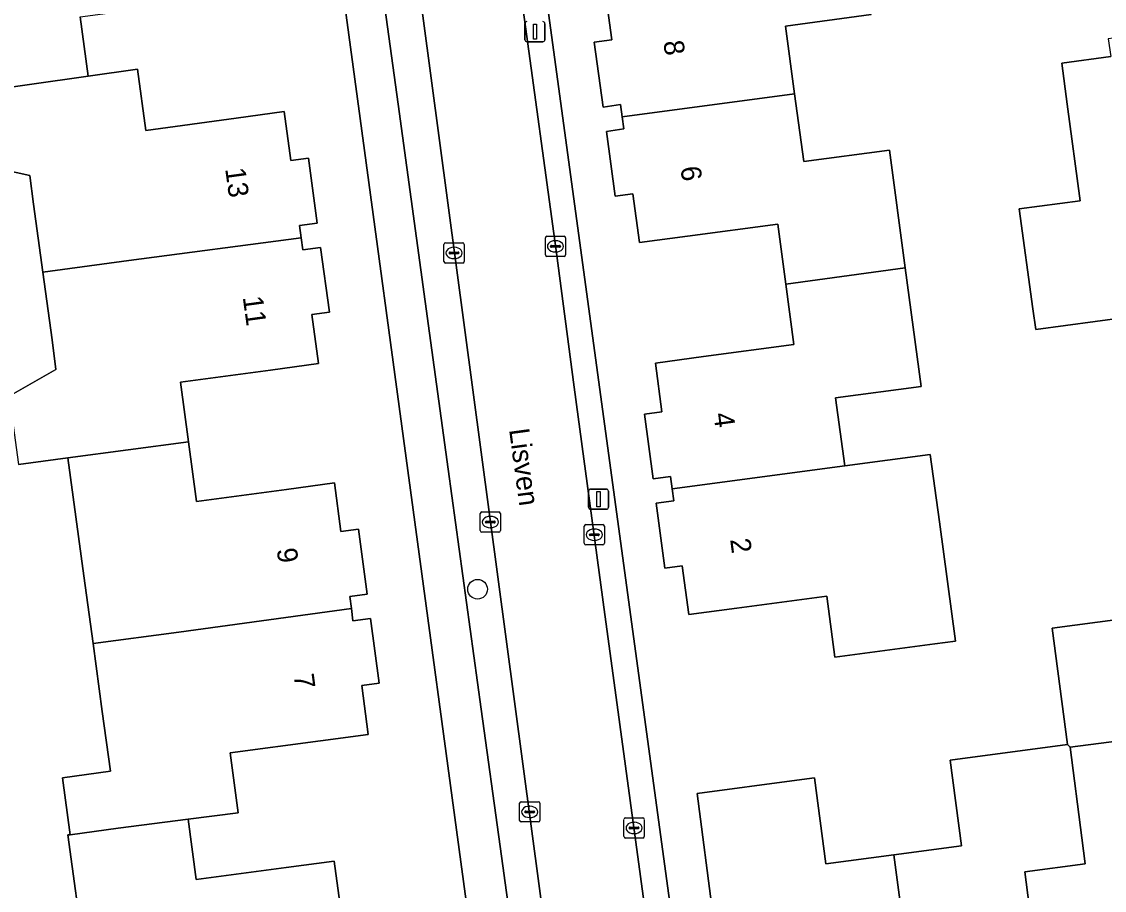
# Model space of a CAD drawing. Extents: x 163426 to 164192, y 380329 to 381641.
# Drawn here: x 163600.9 to 163654.6, y 381389.6 to 381432.7 of the extents above; entities that cross this region are included whole.
import ezdxf

# ---------------------------------------------------------------- set-up
doc = ezdxf.new("R2010")
doc.units = 0
for name, color, linetype in [('IMGEO_Boom', 7, 'Continuous'), ('IMGEO_Erf', 7, 'Continuous'), ('IMGEO_Kolk', 7, 'Continuous'), ('IMGEO_Lichtmast', 7, 'Continuous'), ('IMGEO_Openbare_ruimte_label', 7, 'Continuous'), ('IMGEO_Pand', 7, 'Continuous'), ('IMGEO_Pand_nummerreeks', 7, 'Continuous'), ('IMGEO_Parkeervlak_open', 7, 'Continuous'), ('IMGEO_Rijbaan_lokaal_open', 7, 'Continuous'), ('IMGEO_Voetpad_open', 7, 'Continuous')]:
    doc.layers.add(name, color=color, linetype=linetype)

msp = doc.modelspace()

# ---------------------------------------------------------------- linework, layer by layer
at = {"layer": 'IMGEO_Boom'}
msp.add_circle((163623.502, 381404.563), 0.489, dxfattribs=at)
at = {"layer": 'IMGEO_Erf'}
for points in [[(163625.429, 381370.672), (163614.908, 381448.295)], [(163625.846, 381441.76), (163634.711, 381376.758)], [(163643.031, 381433.061), (163638.779, 381432.489), (163639.232, 381429.12), (163639.683, 381425.765), (163643.935, 381426.337), (163644.72, 381420.495), (163645.51, 381414.622), (163641.264, 381414.051), (163641.717, 381410.682), (163645.964, 381411.246), (163646.413, 381407.908), (163647.209, 381401.991), (163646.189, 381401.855), (163641.232, 381401.193), (163640.825, 381404.228), (163636.359, 381403.629), (163633.98, 381403.31), (163633.66, 381405.731), (163632.79, 381405.616), (163632.365, 381408.827), (163633.235, 381408.942), (163633.155, 381409.544), (163633.075, 381410.148), (163632.206, 381410.033), (163631.781, 381413.244), (163632.65, 381413.359), (163632.33, 381415.78), (163634.709, 381416.099), (163639.196, 381416.7), (163638.794, 381419.697), (163638.396, 381422.67), (163633.909, 381422.069), (163631.53, 381421.75), (163631.2, 381424.173), (163630.33, 381424.054), (163629.892, 381427.268), (163630.762, 381427.387), (163630.68, 381427.989), (163630.598, 381428.593), (163629.728, 381428.475), (163629.29, 381431.689), (163630.16, 381431.807), (163629.83, 381434.23)], [(163603.784, 381432.938), (163604.182, 381430.011), (163606.633, 381430.344), (163607.044, 381427.318), (163611.522, 381427.927), (163613.9, 381428.25), (163614.232, 381425.821), (163615.105, 381425.941), (163615.545, 381422.719), (163614.673, 381422.6), (163614.756, 381421.994), (163614.838, 381421.39), (163615.711, 381421.51), (163616.15, 381418.298), (163615.278, 381418.179), (163615.61, 381415.75), (163613.232, 381415.429), (163608.765, 381414.827), (163609.163, 381411.874), (163609.563, 381408.912), (163614.019, 381409.512), (163616.398, 381409.833), (163616.723, 381407.42), (163617.594, 381407.537), (163618.027, 381404.322), (163617.157, 381404.205), (163617.239, 381403.601), (163617.32, 381402.998), (163618.19, 381403.116), (163618.624, 381399.901), (163617.753, 381399.783), (163618.08, 381397.36), (163615.701, 381397.044), (163611.226, 381396.451), (163611.621, 381393.475), (163609.14, 381393.159), (163609.536, 381390.171), (163614.011, 381390.764), (163616.39, 381391.08), (163616.721, 381388.652)], [(163657.086, 381418.241), (163651.194, 381417.436), (163651.054, 381418.466), (163650.38, 381423.42), (163653.398, 381423.822), (163652.76, 381428.618), (163652.49, 381430.65), (163654.913, 381430.978)], [(163600.263, 381414.138), (163602.585, 381415.466), (163602.388, 381416.923), (163601.932, 381420.287), (163601.476, 381423.658), (163601.284, 381425.078), (163598.705, 381425.644)], [(163602.901, 381395.213), (163605.283, 381395.536), (163604.882, 381398.5), (163604.425, 381401.873), (163603.97, 381405.235), (163603.179, 381411.077), (163600.723, 381410.745)], [(163635.18, 381388.45), (163634.39, 381394.44), (163639.348, 381395.093), (163640.221, 381395.208), (163640.782, 381390.95), (163644.152, 381391.394), (163647.514, 381391.837), (163646.954, 381396.094), (163652.765, 381396.859), (163652.006, 381402.631), (163657.886, 381403.405)], [(163655.84, 381397.119), (163652.894, 381396.738), (163653.477, 381392.239), (163653.644, 381390.947), (163650.648, 381390.559), (163651.232, 381386.05)], [(163603.98, 381386.466), (163603.179, 381392.378), (163603.283, 381392.392), (163602.901, 381395.213)]]:
    msp.add_lwpolyline(points, dxfattribs=at)
at = {"layer": 'IMGEO_Kolk'}
for p, q in [((163626.865, 381421.14), (163626.865, 381421.992)), ((163626.94, 381422.066), (163627.792, 381422.066)), ((163627.353, 381421.846), (163627.378, 381421.846)), ((163627.866, 381421.992), (163627.866, 381421.14)), ((163621.835, 381420.813), (163621.835, 381421.665)), ((163621.91, 381421.739), (163622.762, 381421.739)), ((163622.137, 381421.282), (163622.535, 381421.282)), ((163622.323, 381421.519), (163622.348, 381421.519)), ((163622.836, 381421.665), (163622.836, 381420.813)), ((163627.124, 381421.56), (163627.124, 381421.572)), ((163627.562, 381421.523), (163627.164, 381421.523)), ((163627.167, 381421.609), (163627.565, 381421.609)), ((163627.376, 381421.286), (163627.351, 381421.286)), ((163627.608, 381421.572), (163627.608, 381421.56)), ((163622.762, 381420.739), (163621.91, 381420.739)), ((163622.094, 381421.233), (163622.094, 381421.245)), ((163622.532, 381421.196), (163622.134, 381421.196)), ((163622.346, 381420.959), (163622.321, 381420.959)), ((163622.578, 381421.245), (163622.578, 381421.233)), ((163627.792, 381421.066), (163626.94, 381421.066)), ((163623.71, 381408.394), (163624.562, 381408.394)), ((163623.635, 381407.468), (163623.635, 381408.32)), ((163623.894, 381407.888), (163623.894, 381407.9)), ((163624.332, 381407.851), (163623.934, 381407.851)), ((163623.937, 381407.937), (163624.335, 381407.937)), ((163624.123, 381408.174), (163624.148, 381408.174)), ((163624.378, 381407.9), (163624.378, 381407.888)), ((163624.636, 381408.32), (163624.636, 381407.468)), ((163624.562, 381407.394), (163623.71, 381407.394)), ((163624.146, 381407.614), (163624.121, 381407.614)), ((163628.794, 381406.84), (163628.794, 381407.692)), ((163628.869, 381407.766), (163629.721, 381407.766)), ((163629.096, 381407.309), (163629.494, 381407.309)), ((163629.282, 381407.546), (163629.307, 381407.546)), ((163629.795, 381407.692), (163629.795, 381406.84)), ((163629.721, 381406.766), (163628.869, 381406.766)), ((163629.053, 381407.26), (163629.053, 381407.272)), ((163629.491, 381407.223), (163629.093, 381407.223)), ((163629.305, 381406.986), (163629.28, 381406.986)), ((163629.537, 381407.272), (163629.537, 381407.26)), ((163625.588, 381393.097), (163625.588, 381393.949)), ((163625.663, 381394.023), (163626.515, 381394.023)), ((163626.589, 381393.949), (163626.589, 381393.097)), ((163625.847, 381393.517), (163625.847, 381393.529)), ((163626.285, 381393.48), (163625.887, 381393.48)), ((163625.89, 381393.566), (163626.288, 381393.566)), ((163626.076, 381393.803), (163626.101, 381393.803)), ((163626.331, 381393.529), (163626.331, 381393.517)), ((163626.515, 381393.023), (163625.663, 381393.023)), ((163626.099, 381393.243), (163626.074, 381393.243)), ((163630.766, 381392.302), (163630.766, 381393.154)), ((163630.841, 381393.228), (163631.693, 381393.228)), ((163631.254, 381393.008), (163631.279, 381393.008)), ((163631.767, 381393.154), (163631.767, 381392.302)), ((163631.025, 381392.722), (163631.025, 381392.734)), ((163631.463, 381392.685), (163631.065, 381392.685)), ((163631.068, 381392.771), (163631.466, 381392.771)), ((163631.277, 381392.448), (163631.252, 381392.448)), ((163631.509, 381392.734), (163631.509, 381392.722)), ((163631.693, 381392.228), (163630.841, 381392.228))]:
    msp.add_line(p, q, dxfattribs=at)
for points in [[(163626.865, 381421.14), (163626.865, 381421.992)], [(163626.94, 381422.066), (163627.792, 381422.066)], [(163627.866, 381421.992), (163627.866, 381421.14)], [(163621.835, 381420.813), (163621.835, 381421.665)], [(163621.91, 381421.739), (163622.762, 381421.739)], [(163622.836, 381421.665), (163622.836, 381420.813)], [(163622.762, 381420.739), (163621.91, 381420.739)], [(163627.792, 381421.066), (163626.94, 381421.066)], [(163623.71, 381408.394), (163624.562, 381408.394)], [(163623.635, 381407.468), (163623.635, 381408.32)], [(163624.636, 381408.32), (163624.636, 381407.468)], [(163624.562, 381407.394), (163623.71, 381407.394)], [(163628.794, 381406.84), (163628.794, 381407.692)], [(163628.869, 381407.766), (163629.721, 381407.766)], [(163629.795, 381407.692), (163629.795, 381406.84)], [(163629.721, 381406.766), (163628.869, 381406.766)], [(163625.588, 381393.097), (163625.588, 381393.949)], [(163625.663, 381394.023), (163626.515, 381394.023)], [(163626.589, 381393.949), (163626.589, 381393.097)], [(163626.515, 381393.023), (163625.663, 381393.023)], [(163630.766, 381392.302), (163630.766, 381393.154)], [(163630.841, 381393.228), (163631.693, 381393.228)], [(163631.767, 381393.154), (163631.767, 381392.302)], [(163631.693, 381392.228), (163630.841, 381392.228)]]:
    msp.add_lwpolyline(points, dxfattribs=at)
for centre, radius, start, end in [((163626.942, 381421.99), 0.0765, 91.552, 178.448), ((163626.942, 381421.99), 0.0765, 91.552, 178.448), ((163627.79, 381421.99), 0.0765, 1.552, 88.448), ((163627.79, 381421.99), 0.0765, 1.552, 88.448), ((163621.912, 381421.663), 0.0765, 91.552, 178.448), ((163621.912, 381421.663), 0.0765, 91.552, 178.448), ((163622.134, 381421.242), 0.0403, 85.8775, 175.7526), ((163622.539, 381421.244), 0.0386, 1.7309, 96.639), ((163622.76, 381421.663), 0.0765, 1.552, 88.448), ((163622.76, 381421.663), 0.0765, 1.552, 88.448), ((163627.164, 381421.569), 0.0403, 85.8775, 175.7526), ((163627.161, 381421.559), 0.0366, 178.938, 274.7102), ((163627.565, 381421.566), 0.043, 264.8664, 352.4533), ((163627.569, 381421.571), 0.0386, 1.7309, 96.639), ((163621.912, 381420.815), 0.0765, 181.552, 268.448), ((163621.912, 381420.815), 0.0765, 181.552, 268.448), ((163622.131, 381421.232), 0.0366, 178.938, 274.7102), ((163622.535, 381421.239), 0.043, 264.8664, 352.4533), ((163622.76, 381420.815), 0.0765, 271.552, 358.448), ((163622.76, 381420.815), 0.0765, 271.552, 358.448), ((163626.942, 381421.142), 0.0765, 181.552, 268.448), ((163626.942, 381421.142), 0.0765, 181.552, 268.448), ((163627.79, 381421.142), 0.0765, 271.552, 358.448), ((163627.79, 381421.142), 0.0765, 271.552, 358.448), ((163623.712, 381408.318), 0.0765, 91.552, 178.448), ((163623.712, 381408.318), 0.0765, 91.552, 178.448), ((163624.56, 381408.318), 0.0765, 1.552, 88.448), ((163624.56, 381408.318), 0.0765, 1.552, 88.448), ((163623.934, 381407.897), 0.0403, 85.8775, 175.7526), ((163623.931, 381407.887), 0.0366, 178.938, 274.7102), ((163624.335, 381407.894), 0.043, 264.8664, 352.4533), ((163624.339, 381407.899), 0.0386, 1.7309, 96.639), ((163623.712, 381407.47), 0.0765, 181.552, 268.448), ((163623.712, 381407.47), 0.0765, 181.552, 268.448), ((163624.56, 381407.47), 0.0765, 271.552, 358.448), ((163624.56, 381407.47), 0.0765, 271.552, 358.448), ((163628.871, 381407.69), 0.0765, 91.552, 178.448), ((163628.871, 381407.69), 0.0765, 91.552, 178.448), ((163629.093, 381407.269), 0.0403, 85.8775, 175.7526), ((163629.498, 381407.271), 0.0386, 1.7309, 96.639), ((163629.719, 381407.69), 0.0765, 1.552, 88.448), ((163629.719, 381407.69), 0.0765, 1.552, 88.448), ((163628.871, 381406.842), 0.0765, 181.552, 268.448), ((163628.871, 381406.842), 0.0765, 181.552, 268.448), ((163629.09, 381407.259), 0.0366, 178.938, 274.7102), ((163629.494, 381407.266), 0.043, 264.8664, 352.4533), ((163629.719, 381406.842), 0.0765, 271.552, 358.448), ((163629.719, 381406.842), 0.0765, 271.552, 358.448), ((163625.665, 381393.947), 0.0765, 91.552, 178.448), ((163625.665, 381393.947), 0.0765, 91.552, 178.448), ((163626.513, 381393.947), 0.0765, 1.552, 88.448), ((163626.513, 381393.947), 0.0765, 1.552, 88.448), ((163625.887, 381393.526), 0.0403, 85.8775, 175.7526), ((163625.884, 381393.516), 0.0366, 178.938, 274.7102), ((163626.288, 381393.523), 0.043, 264.8664, 352.4533), ((163626.292, 381393.528), 0.0386, 1.7309, 96.639), ((163625.665, 381393.099), 0.0765, 181.552, 268.448), ((163625.665, 381393.099), 0.0765, 181.552, 268.448), ((163626.513, 381393.099), 0.0765, 271.552, 358.448), ((163626.513, 381393.099), 0.0765, 271.552, 358.448), ((163630.843, 381393.152), 0.0765, 91.552, 178.448), ((163630.843, 381393.152), 0.0765, 91.552, 178.448), ((163631.691, 381393.152), 0.0765, 1.552, 88.448), ((163631.691, 381393.152), 0.0765, 1.552, 88.448), ((163630.843, 381392.304), 0.0765, 181.552, 268.448), ((163630.843, 381392.304), 0.0765, 181.552, 268.448), ((163631.065, 381392.731), 0.0403, 85.8775, 175.7526), ((163631.062, 381392.721), 0.0366, 178.938, 274.7102), ((163631.466, 381392.728), 0.043, 264.8664, 352.4533), ((163631.47, 381392.733), 0.0386, 1.7309, 96.639), ((163631.691, 381392.304), 0.0765, 271.552, 358.448), ((163631.691, 381392.304), 0.0765, 271.552, 358.448)]:
    msp.add_arc(centre, radius, start, end, dxfattribs=at)
for centre, major_axis, ratio, start_param, end_param in [((163627.352, 381421.566), (-0.387, 0.002), 0.722429, 4.712389, 7.853982), ((163627.377, 381421.566), (-0.39, 0.002), 0.717154, 1.570796, 4.712389), ((163622.322, 381421.239), (-0.387, 0.002), 0.722429, 4.712389, 7.853982), ((163622.347, 381421.239), (-0.39, 0.002), 0.717154, 1.570796, 4.712389), ((163624.122, 381407.894), (-0.387, 0.002), 0.722429, 4.712389, 7.853982), ((163624.147, 381407.894), (-0.39, 0.002), 0.717154, 1.570796, 4.712389), ((163629.281, 381407.266), (-0.387, 0.002), 0.722429, 4.712389, 7.853982), ((163629.306, 381407.266), (-0.39, 0.002), 0.717154, 1.570796, 4.712389), ((163626.075, 381393.523), (-0.387, 0.002), 0.722429, 4.712389, 7.853982), ((163626.1, 381393.523), (-0.39, 0.002), 0.717154, 1.570796, 4.712389), ((163631.253, 381392.728), (-0.387, 0.002), 0.722429, 4.712389, 7.853982), ((163631.278, 381392.728), (-0.39, 0.002), 0.717154, 1.570796, 4.712389)]:
    msp.add_ellipse(centre, major_axis=major_axis, ratio=ratio, start_param=start_param, end_param=end_param, dxfattribs=at)
at = {"layer": 'IMGEO_Lichtmast'}
for p, q in [((163625.849, 381431.807), (163625.849, 381432.607)), ((163625.849, 381432.607), (163625.849, 381431.807)), ((163626.839, 381432.607), (163626.839, 381431.807)), ((163626.839, 381431.807), (163626.839, 381432.607)), ((163626.739, 381431.707), (163625.949, 381431.707)), ((163625.949, 381431.707), (163626.739, 381431.707)), ((163629.106, 381409.527), (163629.896, 381409.527)), ((163629.896, 381409.527), (163629.106, 381409.527)), ((163629.006, 381408.627), (163629.006, 381409.427)), ((163629.006, 381409.427), (163629.006, 381408.627)), ((163629.996, 381409.427), (163629.996, 381408.627)), ((163629.996, 381408.627), (163629.996, 381409.427)), ((163629.896, 381408.527), (163629.106, 381408.527)), ((163629.106, 381408.527), (163629.896, 381408.527))]:
    msp.add_line(p, q, dxfattribs=at)
for points in [[(163626.269, 381432.582), (163626.419, 381432.582), (163626.419, 381431.832), (163626.269, 381431.832), (163626.269, 381432.582)], [(163629.426, 381409.402), (163629.576, 381409.402), (163629.576, 381408.652), (163629.426, 381408.652), (163629.426, 381409.402)]]:
    msp.add_lwpolyline(points, dxfattribs=at)
for centre, start, end in [((163625.949, 381432.607), 90, 180), ((163625.949, 381432.607), 90, 180), ((163626.739, 381432.607), 0, 90), ((163626.739, 381432.607), 360, 90), ((163625.949, 381431.807), 180, 270), ((163625.949, 381431.807), 180, 270), ((163626.739, 381431.807), 270, 0), ((163626.739, 381431.807), 270, 0), ((163629.106, 381409.427), 90, 180), ((163629.106, 381409.427), 90, 180), ((163629.896, 381409.427), 0, 90), ((163629.896, 381409.427), 360, 90), ((163629.106, 381408.627), 180, 270), ((163629.106, 381408.627), 180, 270), ((163629.896, 381408.627), 270, 0), ((163629.896, 381408.627), 270, 0)]:
    msp.add_arc(centre, 0.1, start, end, dxfattribs=at)
at = {"layer": 'IMGEO_Pand'}
for points in [[(163604.182, 381430.011), (163603.784, 381432.938), (163608.262, 381433.547), (163610.64, 381433.87), (163610.31, 381436.291), (163611.179, 381436.409), (163610.742, 381439.611), (163609.873, 381439.492), (163609.79, 381440.096), (163601.242, 381438.946), (163601.697, 381435.579), (163597.438, 381435.003), (163598.229, 381429.159)], [(163639.232, 381429.12), (163638.779, 381432.489), (163643.031, 381433.061), (163642.906, 381433.995), (163642.24, 381438.95), (163636.27, 381438.18), (163636.67, 381435.15), (163632.189, 381434.547), (163629.83, 381434.23), (163630.16, 381431.807), (163629.29, 381431.689), (163629.728, 381428.475), (163630.598, 381428.593), (163630.68, 381427.989)], [(163658.731, 381431.496), (163658.127, 381431.414), (163658.009, 381432.284), (163654.795, 381431.849), (163654.913, 381430.978), (163652.49, 381430.65), (163652.76, 381428.618), (163653.398, 381423.822), (163650.38, 381423.42), (163651.054, 381418.466), (163651.194, 381417.436), (163657.086, 381418.241), (163656.503, 381422.506), (163659.871, 381422.966)], [(163614.756, 381421.994), (163614.673, 381422.6), (163615.545, 381422.719), (163615.105, 381425.941), (163614.232, 381425.821), (163613.9, 381428.25), (163611.522, 381427.927), (163607.044, 381427.318), (163606.633, 381430.344), (163604.182, 381430.011), (163598.229, 381429.159), (163598.705, 381425.644), (163601.284, 381425.078), (163601.476, 381423.658), (163601.932, 381420.287), (163606.191, 381420.865)], [(163639.232, 381429.12), (163630.68, 381427.989), (163630.762, 381427.387), (163629.892, 381427.268), (163630.33, 381424.054), (163631.2, 381424.173), (163631.53, 381421.75), (163633.909, 381422.069), (163638.396, 381422.67), (163638.794, 381419.697), (163644.72, 381420.495), (163643.935, 381426.337), (163639.683, 381425.765)], [(163614.756, 381421.994), (163606.191, 381420.865), (163601.932, 381420.287), (163602.388, 381416.923), (163602.585, 381415.466), (163600.263, 381414.138), (163600.723, 381410.745), (163603.179, 381411.077), (163609.163, 381411.874), (163608.765, 381414.827), (163613.232, 381415.429), (163615.61, 381415.75), (163615.278, 381418.179), (163616.15, 381418.298), (163615.711, 381421.51), (163614.838, 381421.39)], [(163638.794, 381419.697), (163639.196, 381416.7), (163634.709, 381416.099), (163632.33, 381415.78), (163632.65, 381413.359), (163631.781, 381413.244), (163632.206, 381410.033), (163633.075, 381410.148), (163633.155, 381409.544), (163641.717, 381410.682), (163641.264, 381414.051), (163645.51, 381414.622), (163644.72, 381420.495)], [(163604.425, 381401.873), (163608.685, 381402.443), (163617.239, 381403.601), (163617.157, 381404.205), (163618.027, 381404.322), (163617.594, 381407.537), (163616.723, 381407.42), (163616.398, 381409.833), (163614.019, 381409.512), (163609.563, 381408.912), (163609.163, 381411.874), (163603.179, 381411.077), (163603.97, 381405.235)], [(163646.413, 381407.908), (163645.964, 381411.246), (163641.717, 381410.682), (163633.155, 381409.544), (163633.235, 381408.942), (163632.365, 381408.827), (163632.79, 381405.616), (163633.66, 381405.731), (163633.98, 381403.31), (163636.359, 381403.629), (163640.825, 381404.228), (163641.232, 381401.193), (163646.189, 381401.855), (163647.209, 381401.991)], [(163617.753, 381399.783), (163618.624, 381399.901), (163618.19, 381403.116), (163617.32, 381402.998), (163617.239, 381403.601), (163608.685, 381402.443), (163604.425, 381401.873), (163604.882, 381398.5), (163605.283, 381395.536), (163602.901, 381395.213), (163603.283, 381392.392), (163605.665, 381392.716), (163609.14, 381393.159), (163611.621, 381393.475), (163611.226, 381396.451), (163615.701, 381397.044), (163618.08, 381397.36)], [(163652.765, 381396.859), (163652.894, 381396.738), (163655.84, 381397.119), (163656.422, 381392.62), (163656.73, 381390.24), (163659.157, 381390.559), (163659.271, 381389.687), (163662.48, 381390.108), (163662.366, 381390.98), (163662.97, 381391.059), (163661.817, 381399.592), (163658.447, 381399.148), (163657.886, 381403.405), (163652.006, 381402.631)], [(163644.152, 381391.394), (163645.29, 381382.84), (163645.896, 381382.92), (163646.011, 381382.047), (163649.225, 381382.469), (163649.109, 381383.35), (163651.54, 381383.67), (163651.232, 381386.05), (163650.648, 381390.559), (163653.644, 381390.947), (163653.477, 381392.239), (163652.894, 381396.738), (163652.765, 381396.859), (163646.954, 381396.094), (163647.514, 381391.837)], [(163644.152, 381391.394), (163640.782, 381390.95), (163640.221, 381395.208), (163639.348, 381395.093), (163634.39, 381394.44), (163635.18, 381388.45), (163638.13, 381388.83), (163638.729, 381384.398), (163639.05, 381382.02), (163641.471, 381382.338), (163641.586, 381381.465), (163644.8, 381381.888), (163644.685, 381382.761), (163645.29, 381382.84)], [(163616.39, 381391.08), (163614.011, 381390.764), (163609.536, 381390.171), (163609.14, 381393.159), (163605.665, 381392.716), (163603.283, 381392.392), (163603.179, 381392.378), (163603.98, 381386.466), (163604.436, 381383.098), (163608.695, 381383.674), (163617.24, 381384.835), (163617.158, 381385.44), (163618.03, 381385.559), (163617.593, 381388.77), (163616.721, 381388.652)]]:
    msp.add_lwpolyline(points, close=True, dxfattribs=at)
at = {"layer": 'IMGEO_Parkeervlak_open'}
for points in [[(163627.821, 381380.451), (163619.545, 381442.291)], [(163618.084, 381439.336), (163618.633, 381435.348), (163619.56, 381428.613), (163621.122, 381417.258), (163622.049, 381410.522), (163623.687, 381398.624), (163624.624, 381391.812), (163625.897, 381382.561), (163626.191, 381382.287)]]:
    msp.add_lwpolyline(points, dxfattribs=at)
at = {"layer": 'IMGEO_Rijbaan_lokaal_open'}
for points in [[(163619.545, 381442.291), (163627.821, 381380.451), (163628.729, 381373.668)], [(163633.362, 381377.317), (163630.333, 381399.565), (163629.821, 381403.315), (163628.293, 381414.585), (163627.397, 381421.367), (163625.758, 381433.293), (163625.234, 381437.074), (163624.735, 381441.021)]]:
    msp.add_lwpolyline(points, dxfattribs=at)
at = {"layer": 'IMGEO_Voetpad_open'}
for points in [[(163630.266, 381453.591), (163613.945, 381456.243), (163614.915, 381448.711), (163614.908, 381448.295), (163625.429, 381370.672)], [(163634.711, 381376.758), (163625.846, 381441.76)], [(163624.735, 381441.021), (163625.234, 381437.074), (163625.758, 381433.293), (163627.397, 381421.367), (163628.293, 381414.585), (163629.821, 381403.315), (163630.333, 381399.565), (163633.362, 381377.317)], [(163623.687, 381398.624), (163622.049, 381410.522), (163621.122, 381417.258), (163619.56, 381428.613), (163618.633, 381435.348), (163618.084, 381439.336)], [(163626.191, 381382.287), (163625.897, 381382.561), (163624.624, 381391.812), (163623.687, 381398.624)]]:
    msp.add_lwpolyline(points, dxfattribs=at)

# ---------------------------------------------------------------- texts
at = {"layer": 'IMGEO_Openbare_ruimte_label'}
msp.add_text('Lisven', height=1, rotation=277.7007, dxfattribs=at).set_placement((163625.063, 381412.479))
at = {"layer": 'IMGEO_Pand_nummerreeks'}
for s, rotation, p in [('8', 277.757, (163632.715, 381431.718)), ('13', 277.7897, (163610.977, 381425.409)), ('6', 277.757, (163633.564, 381425.482)), ('11', 277.7897, (163611.848, 381419.046)), ('4', 277.5375, (163635.204, 381413.266)), ('2', 277.5399, (163636.03, 381407.033)), ('9', 277.6801, (163613.532, 381406.549)), ('7', 277.6774, (163614.373, 381400.314))]:
    msp.add_text(s, height=1, rotation=rotation, dxfattribs=at).set_placement(p)

doc.saveas('drawing.dxf')
